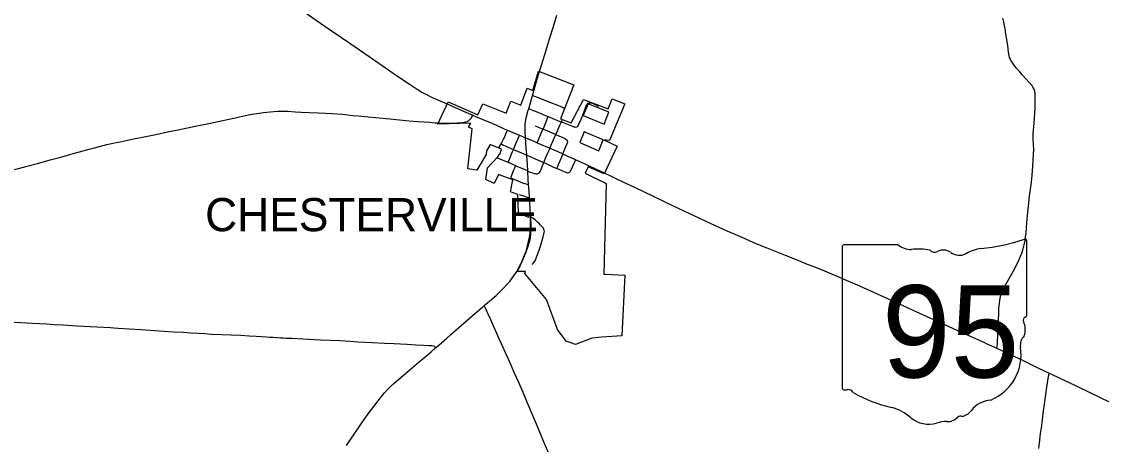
# Model space of a CAD drawing. Extents: x 1815539 to 1947826, y 273303 to 993194.
# Drawn here: x 1909861 to 1926135, y 898782 to 905160 of the extents above; entities that cross this region are included whole.
import ezdxf

# ---------------------------------------------------------------- set-up
doc = ezdxf.new("R2010")
doc.units = 0
for name, color, linetype in [('GM_X_City_Street', 7, 'Continuous'), ('GM_X_Corporation', 7, 'Continuous'), ('GM_X_Corporation_Text', 7, 'Continuous'), ('GM_X_County_Road', 7, 'Continuous'), ('GM_X_State_Route', 7, 'Continuous'), ('GM_X_Township_Road', 7, 'Continuous'), ('SC_Shading3', 7, 'Continuous')]:
    doc.layers.add(name, color=color, linetype=linetype)

msp = doc.modelspace()

# ---------------------------------------------------------------- linework, layer by layer
at = {"layer": 'GM_X_City_Street'}
for points in [[(1917561, 904044), (1917592, 904033), (1917670, 904005), (1917732, 903981), (1917824, 903943), (1917979, 903882), (1918010, 903871), (1918025, 903864), (1918039, 903855), (1918048, 903847)], [(1917996, 903648), (1918029, 903638), (1918075, 903620), (1918151, 903586), (1918166, 903580), (1918182, 903574), (1918198, 903570), (1918214, 903569), (1918230, 903574), (1918243, 903584), (1918254, 903597), (1918261, 903612), (1918293, 903688), (1918318, 903750), (1918359, 903857), (1918371, 903888), (1918379, 903903), (1918388, 903916), (1918401, 903927), (1918416, 903933), (1918432, 903936), (1918449, 903934), (1918465, 903929), (1918495, 903916), (1918554, 903886)], [(1916149, 903631), (1916248, 903628), (1916348, 903629), (1916431, 903632), (1916496, 903637), (1916529, 903641), (1916545, 903643), (1916560, 903648), (1916575, 903653), (1916584, 903657), (1916591, 903661), (1916601, 903667), (1916612, 903676), (1916623, 903686), (1916632, 903696), (1916641, 903708), (1916648, 903721), (1916664, 903747)], [(1917504, 903846), (1917528, 903838), (1917570, 903821), (1917616, 903804), (1917710, 903765), (1917769, 903740), (1917797, 903728)], [(1917720, 903539), (1917736, 903574), (1917767, 903648), (1917789, 903708), (1917797, 903728)], [(1917797, 903728), (1917830, 903715), (1917905, 903685), (1917965, 903660), (1917996, 903648)], [(1917599, 903589), (1917660, 903564), (1917720, 903539)], [(1917914, 903457), (1917937, 903512), (1917975, 903599), (1917996, 903648)], [(1917996, 903648), (1917997, 903650), (1918012, 903687)], [(1917087, 903315), (1917109, 903354), (1917126, 903385), (1917140, 903413), (1917156, 903451), (1917166, 903478), (1917179, 903513), (1917183, 903523)], [(1917277, 903231), (1917305, 903305), (1917354, 903423), (1917364, 903446)], [(1917631, 903333), (1917646, 903368), (1917703, 903501), (1917720, 903539)], [(1917720, 903539), (1917750, 903527), (1917855, 903483), (1917914, 903457)], [(1917824, 903249), (1917839, 903287), (1917910, 903447), (1917914, 903457)], [(1917914, 903457), (1917960, 903436), (1918020, 903409), (1918049, 903395), (1918063, 903386), (1918074, 903375), (1918083, 903362), (1918089, 903348), (1918091, 903337)], [(1917053, 903257), (1917087, 903315)], [(1917087, 903315), (1917113, 903303), (1917157, 903282), (1917277, 903231)], [(1917195, 903038), (1917214, 903087), (1917262, 903199), (1917277, 903231)], [(1917277, 903231), (1917397, 903180), (1917475, 903146)], [(1917731, 903035), (1917769, 903125), (1917794, 903182), (1917816, 903230), (1917824, 903249)], [(1918019, 903163), (1918065, 903275), (1918085, 903319), (1918091, 903337)], [(1917029, 903107), (1917032, 903105), (1917037, 903102), (1917044, 903099), (1917071, 903089), (1917162, 903052), (1917195, 903038)], [(1917475, 903146), (1917590, 903095), (1917694, 903051), (1917731, 903035)], [(1917929, 902945), (1917937, 902963), (1917955, 903006), (1917973, 903049), (1918016, 903156), (1918019, 903163)], [(1918094, 902880), (1918111, 902883), (1918125, 902892), (1918135, 902904), (1918150, 902934), (1918170, 902980), (1918190, 903026), (1918204, 903053), (1918215, 903076)], [(1917195, 903038), (1917248, 903013), (1917305, 902988)], [(1917240, 902798), (1917239, 902802), (1917239, 902806), (1917240, 902811), (1917241, 902816), (1917282, 902922), (1917293, 902953), (1917305, 902988)], [(1917305, 902988), (1917334, 902976), (1917384, 902955), (1917426, 902938), (1917446, 902931), (1917461, 902925), (1917474, 902918), (1917490, 902905)], [(1917490, 902905), (1917512, 902896), (1917559, 902879), (1917587, 902870), (1917602, 902866), (1917618, 902863), (1917626, 902862), (1917635, 902863)], [(1917635, 902863), (1917643, 902866), (1917654, 902872), (1917665, 902882), (1917678, 902900), (1917690, 902931), (1917703, 902961), (1917731, 903035)], [(1917731, 903035), (1917766, 903018), (1917869, 902971), (1917929, 902945)], [(1917929, 902945), (1917956, 902933), (1918001, 902915), (1918046, 902896), (1918088, 902880), (1918094, 902880)], [(1917240, 902798), (1917278, 902782), (1917338, 902757), (1917408, 902730), (1917463, 902712), (1917502, 902702)], [(1917359, 902551), (1917406, 902536), (1917424, 902530), (1917482, 902512), (1917516, 902502)], [(1917557, 901496), (1917587, 901533), (1917596, 901547), (1917604, 901561), (1917617, 901590), (1917628, 901621), (1917661, 901713), (1917681, 901774), (1917721, 901914), (1917738, 901977), (1917741, 901997), (1917739, 902011), (1917733, 902028), (1917725, 902042), (1917711, 902058), (1917698, 902075), (1917683, 902091), (1917661, 902115), (1917636, 902136), (1917599, 902168), (1917564, 902196), (1917555, 902202), (1917548, 902203), (1917533, 902203)]]:
    msp.add_lwpolyline(points, dxfattribs=at)
at = {"layer": 'GM_X_Corporation'}
for points in [[(1916721, 902918), (1916584, 902938), (1916654, 903543), (1916599, 903568), (1916631, 903626), (1916135, 903615), (1916288, 903951), (1916735, 903752), (1916814, 903917), (1917165, 903776), (1917235, 903959), (1917385, 903901), (1917482, 904153), (1917566, 904121), (1917650, 904410), (1918182, 904204), (1917985, 903695), (1918143, 903631), (1918332, 903987), (1918701, 903844), (1918764, 903997), (1918954, 903920), (1918724, 903365), (1918634, 903376), (1918838, 903282), (1918643, 902861), (1918401, 902967), (1918357, 902876), (1918671, 902719), (1918636, 901348), (1918654, 901348), (1918954, 901337), (1918907, 900420), (1918605, 900399), (1918453, 900386), (1918207, 900289), (1918069, 900338), (1917940, 900518), (1917772, 900966), (1917448, 901359), (1917457, 901388), (1917327, 901389), (1917348, 901423), (1917399, 901529), (1917464, 901686), (1917491, 901757), (1917517, 901838), (1917529, 901891), (1917543, 902040), (1917535, 902243), (1917506, 902241), (1917503, 902207), (1917349, 902273), (1917342, 902550), (1917230, 902590), (1917265, 902771), (1917048, 902854), (1916983, 902716), (1916860, 902776), (1916885, 902954), (1917033, 903113), (1917037, 903116), (1917058, 903162), (1917067, 903157), (1917096, 903235), (1916923, 903308), (1916866, 903208), (1916861, 903155)], [(1918324, 903745), (1918639, 903615), (1918714, 903796), (1918399, 903917)], [(1918276, 903338), (1918562, 903209), (1918627, 903378), (1918342, 903496)]]:
    msp.add_lwpolyline(points, close=True, dxfattribs=at)
at = {"layer": 'GM_X_County_Road'}
for points in [[(1912731, 903635), (1912752, 903640), (1913105, 903715), (1913233, 903742), (1913330, 903762), (1913411, 903775), (1913508, 903789), (1913606, 903799), (1913665, 903803)], [(1913665, 903803), (1913721, 903807), (1913770, 903809), (1913836, 903808), (1913881, 903807), (1913982, 903801), (1914073, 903794), (1914196, 903787), (1914332, 903781), (1914442, 903778), (1914539, 903775), (1914616, 903770), (1914695, 903763), (1914774, 903755), (1914855, 903744), (1914936, 903736), (1915082, 903723), (1915197, 903713), (1915409, 903693), (1915556, 903679), (1915703, 903665), (1915833, 903653), (1916013, 903641), (1916095, 903634), (1916149, 903631)], [(1909738, 902923), (1909944, 902978), (1910102, 903020), (1910292, 903073), (1910450, 903116), (1910640, 903168), (1910735, 903194), (1910877, 903233), (1910940, 903251), (1911035, 903277), (1911147, 903305), (1911259, 903330), (1911371, 903353), (1911500, 903379), (1911757, 903433), (1911885, 903459), (1912062, 903495), (1912223, 903528), (1912528, 903592), (1912656, 903620), (1912731, 903635)], [(1925193, 898722), (1925202, 898803), (1925219, 898949), (1925230, 899030), (1925264, 899290), (1925277, 899388), (1925291, 899501), (1925313, 899647), (1925335, 899776), (1925343, 899825), (1925350, 899857)]]:
    msp.add_lwpolyline(points, dxfattribs=at)
at = {"layer": 'GM_X_State_Route'}
for points in [[(1910495, 907783), (1910557, 907740), (1910747, 907611), (1911086, 907380), (1911330, 907214), (1911560, 907057), (1911873, 906846), (1912198, 906624), (1912442, 906458), (1912700, 906282), (1912890, 906153), (1913214, 905930), (1913444, 905772), (1913742, 905568), (1913903, 905456), (1914417, 905102), (1914809, 904833), (1915246, 904533)], [(1917667, 904406), (1917748, 904663), (1917829, 904929), (1917872, 905070), (1917927, 905258)], [(1915246, 904533), (1915296, 904498), (1915524, 904339), (1915701, 904219), (1915824, 904139), (1915894, 904096), (1915952, 904065), (1916040, 904021), (1916144, 903974), (1916276, 903917)], [(1917457, 903408), (1917452, 903498), (1917450, 903564), (1917451, 903614), (1917454, 903647), (1917459, 903680), (1917471, 903728), (1917497, 903823), (1917504, 903846), (1917561, 904044), (1917570, 904077), (1917582, 904116), (1917602, 904187), (1917638, 904312), (1917667, 904406)], [(1916276, 903917), (1916395, 903866), (1916430, 903850)], [(1916430, 903850), (1916532, 903804), (1916664, 903747), (1916726, 903720), (1916896, 903647), (1917016, 903595), (1917136, 903543), (1917183, 903523), (1917256, 903491), (1917364, 903446), (1917457, 903408)], [(1917457, 903408), (1917570, 903359), (1917631, 903333), (1917668, 903317), (1917811, 903255), (1917824, 903249), (1917941, 903198), (1918019, 903163), (1918100, 903127), (1918190, 903088), (1918215, 903076), (1918293, 903040), (1918413, 902985), (1918511, 902939), (1918651, 902872)], [(1917471, 903214), (1917468, 903246), (1917462, 903343), (1917457, 903408)], [(1917531, 902242), (1917526, 902339), (1917516, 902502), (1917509, 902601), (1917502, 902702), (1917497, 902778), (1917490, 902905), (1917486, 903004), (1917477, 903133), (1917475, 903146), (1917471, 903214)], [(1918651, 902872), (1918738, 902831), (1918798, 902802), (1918932, 902738), (1919110, 902655), (1919380, 902525)], [(1919380, 902525), (1919672, 902386), (1919938, 902259), (1920251, 902114), (1920490, 902006), (1920670, 901926), (1920926, 901815), (1921092, 901746), (1921367, 901637), (1921535, 901570), (1921702, 901503), (1921802, 901464)], [(1917324, 901392), (1917352, 901441), (1917383, 901499), (1917411, 901559), (1917442, 901635), (1917464, 901697), (1917487, 901776), (1917503, 901841), (1917515, 901906), (1917524, 901971), (1917529, 902037), (1917533, 902152), (1917533, 902203), (1917531, 902242)], [(1921802, 901464), (1921961, 901401), (1922068, 901357), (1922324, 901247), (1922488, 901173), (1922758, 901053), (1923011, 900937), (1923340, 900789), (1923549, 900694), (1923758, 900597), (1923967, 900502), (1924236, 900381), (1924363, 900323)], [(1916835, 900879), (1916911, 900944), (1917011, 901029), (1917071, 901084), (1917129, 901142), (1917185, 901202), (1917217, 901239), (1917257, 901291), (1917303, 901359), (1917324, 901392)], [(1914757, 898764), (1914885, 898954), (1915023, 899158), (1915100, 899265), (1915218, 899422), (1915278, 899500), (1915331, 899563), (1915387, 899623), (1915422, 899658), (1915471, 899702), (1915583, 899799), (1915683, 899883), (1915858, 900031), (1915908, 900074), (1916033, 900180), (1916106, 900243), (1916107, 900245), (1916268, 900385), (1916329, 900440), (1916526, 900612), (1916688, 900751), (1916811, 900859), (1916835, 900879)], [(1924363, 900323), (1924400, 900306), (1924560, 900233), (1924579, 900224), (1924772, 900134), (1924935, 900056), (1925186, 899935), (1925350, 899857), (1925393, 899837), (1925763, 899659), (1925970, 899560), (1926251, 899426)]]:
    msp.add_lwpolyline(points, dxfattribs=at)
at = {"layer": 'GM_X_Township_Road'}
for points in [[(1924560, 900233), (1924564, 900270), (1924567, 900302), (1924574, 900450), (1924587, 900761), (1924591, 900843), (1924597, 900909), (1924603, 900957), (1924613, 901006), (1924621, 901037), (1924632, 901068), (1924651, 901113), (1924674, 901157), (1924747, 901285), (1924812, 901400), (1924858, 901487), (1924893, 901561), (1924918, 901621), (1924935, 901667), (1924955, 901730), (1924971, 901794), (1924985, 901858), (1924993, 901906), (1924999, 901972), (1925017, 902184), (1925031, 902331), (1925054, 902527), (1925082, 902738), (1925091, 902836), (1925102, 902983), (1925109, 903065), (1925114, 903163), (1925115, 903229), (1925112, 903310), (1925109, 903392), (1925109, 903458), (1925112, 903523), (1925121, 903621), (1925128, 903703), (1925134, 903785), (1925136, 903850), (1925138, 904047), (1925136, 904080), (1925133, 904096), (1925130, 904112), (1925125, 904128), (1925119, 904143), (1925112, 904158), (1925104, 904172), (1925085, 904199), (1925053, 904236), (1924998, 904297), (1924942, 904357), (1924899, 904406), (1924856, 904455), (1924816, 904506), (1924788, 904546), (1924771, 904573), (1924764, 904588), (1924758, 904603), (1924752, 904618), (1924744, 904650), (1924735, 904698), (1924723, 904795), (1924715, 904860), (1924697, 904972), (1924683, 905052), (1924666, 905149), (1924651, 905213)], [(1917807, 898646), (1917741, 898796), (1917691, 898917), (1917636, 899054), (1917591, 899159), (1917546, 899265), (1917450, 899491), (1917418, 899567), (1917353, 899717), (1917287, 899867), (1917233, 899986), (1917193, 900076), (1917134, 900211), (1917093, 900300), (1917060, 900375), (1917020, 900465), (1916933, 900659), (1916892, 900748), (1916853, 900838), (1916835, 900879)], [(1909664, 900631), (1910025, 900611), (1910237, 900599), (1910352, 900592), (1910483, 900584), (1910706, 900572), (1910893, 900561), (1911203, 900544), (1911251, 900539), (1911316, 900534), (1911480, 900524), (1911660, 900514), (1912004, 900492), (1912152, 900482), (1912299, 900473), (1912413, 900465), (1912528, 900459), (1912626, 900453), (1912724, 900447), (1912880, 900442), (1913021, 900435), (1913163, 900428), (1913292, 900421), (1913398, 900415), (1913476, 900410), (1913548, 900406), (1913604, 900401), (1913650, 900398), (1913720, 900395), (1913770, 900392), (1913803, 900390), (1913843, 900387), (1913879, 900386), (1913908, 900384), (1913934, 900383), (1914021, 900378), (1914102, 900375), (1914366, 900362), (1914661, 900348), (1914811, 900339), (1914927, 900332), (1915147, 900320), (1915329, 900312), (1915471, 900304), (1915572, 900299), (1915673, 900294), (1915801, 900286), (1915919, 900279), (1915993, 900276), (1916044, 900273), (1916069, 900268), (1916082, 900264), (1916091, 900256), (1916106, 900243)]]:
    msp.add_lwpolyline(points, dxfattribs=at)
at = {"layer": 'SC_Shading3'}
for p, q in [((1923071, 901792), (1922255, 901792)), ((1925012, 900739), (1925012, 901844)), ((1922228, 901756), (1922228, 899642)), ((1925012, 900739), (1925012, 900739))]:
    msp.add_line(p, q, dxfattribs=at)
for centre, radius, start, end in [((1922260, 901760), 32.3, 98.1301, 188.1301), ((1923265, 902037), 313, 231.6195, 271.1119), ((1924020, 904673), 2953, 275.8445, 288.9065), ((1924981, 901849), 31, 351.8621, 97.738), ((1923368, 900606), 1123, 80.4867, 94.9883), ((1923623, 901771), 90.3, 219.7921, 297.1024), ((1923756, 901527), 188, 54.4667, 119.1411), ((1923998, 901862), 226, 233.8562, 294.8282), ((1924397, 901147), 594, 97.3462, 120.7689), ((1925005, 900658), 48, 107.944, 210.337), ((1924700, 900518), 288, 340.033, 23.6496), ((1924979, 900735), 33.2, 289.6038, 7.7341), ((1925123, 900276), 210, 136.8065, 186.9296), ((1924186, 900136), 739, 292.3089, 8.9858), ((1922260, 899638), 32.5, 171.9584, 258.3066), ((1922265, 899854), 248, 267.339, 280.6039), ((1922316, 899520), 89.5, 29.7484, 93.2717), ((1923446, 901419), 2132, 240.4129, 257.1985), ((1922811, 898693), 667, 47.1842, 75.836), ((1924497, 899049), 404, 94.4031, 142.5768), ((1923532, 899510), 423, 230.7004, 286.2918), ((1923808, 899352), 226, 268.777, 315.5493), ((1924012, 899147), 63.5, 65.7517, 132.6484), ((1923985, 899438), 239, 282.8732, 323.2771), ((1923777, 898779), 348, 85.6951, 111.2099)]:
    msp.add_arc(centre, radius, start, end, dxfattribs=at)

# ---------------------------------------------------------------- texts
at = {"layer": 'GM_X_Corporation_Text'}
msp.add_text('CHESTERVILLE', height=500, rotation=0, dxfattribs=at).set_placement((1912627, 901998))
at = {"layer": 'SC_Shading3'}
msp.add_text('95', height=1392.2, dxfattribs=at).set_placement((1922828, 899791))

doc.saveas('drawing.dxf')
